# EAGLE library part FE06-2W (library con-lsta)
FEMALE HEADER
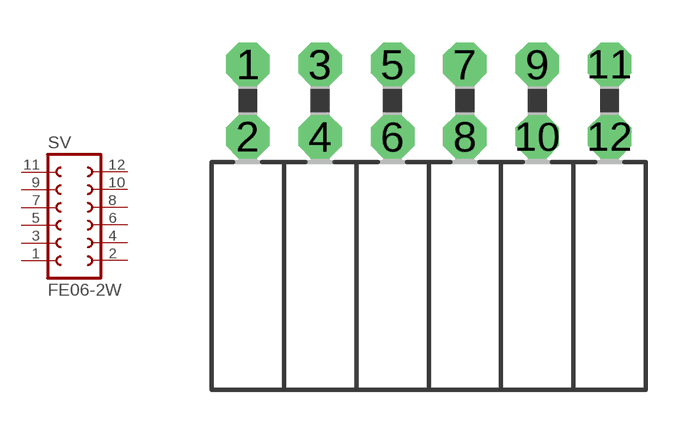
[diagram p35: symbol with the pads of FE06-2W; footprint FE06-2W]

Designator prefix SV

## FE06-2W (OC_FARNELL: unknown; OC_NEWARK: unknown)  [FE06-2W]
1  1  pas
2  2  pas
3  3  pas
4  4  pas
5  5  pas
6  6  pas
7  7  pas
8  8  pas
9  9  pas
10  10  pas
11  11  pas
12  12  pas

## Footprint FE06-2W (pad centres in mm)
FEMALE HEADER
drill 1.016 octagon: 1 -6.35,1.27; 2 -6.35,-1.27; 3 -3.81,1.27; 4 -3.81,-1.27; 5 -1.27,1.27; 6 -1.27,-1.27; 7 1.27,1.27; 8 1.27,-1.27; 9 3.81,1.27; 10 3.81,-1.27; 11 6.35,1.27; 12 6.35,-1.27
